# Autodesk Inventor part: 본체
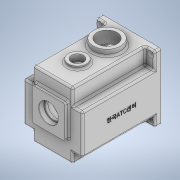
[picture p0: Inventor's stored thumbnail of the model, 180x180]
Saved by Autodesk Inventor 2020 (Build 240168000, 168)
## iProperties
Created: 2022-01
Part Number: 본체
Material: 일반
Document SubType Name: Modeling
Designer: user
Density: 1 g/cm^3
Appearance: 기본값
Author: user
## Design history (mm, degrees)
sketch "스케치5"
  geometry: L1 (-49, -55)-(49, -55); L2 (49, -55)-(49, 55); L3 (49, 55)-(-49, 55); L4 (-49, 55)-(-49, -55); L5 (-49, -55)-(49, 55); L6 (49, -55)-(-49, 55); 1 further point
  constraints: 12 end point, 2 midpoint, 2 parallel, 1 horizontal, 1 perpendicular
  dimensions: "d27" = 98 distance of L3.end L2.end; "d28" = 110 distance of L2.end L1.end
extrude "돌출6" new body sketch "스케치5" stored distance "d29" = 130; taper "d30" = 0 deg
sketch "스케치7"
  geometry: L1 (-49, 55)-(-49, -55) reference; L2 (-49, 55)-(-33, 55); L3 (-33, 55)-(-33, 28); L4 (-33, 28)-(-49, 28); L5 (-49, 28)-(-49, 55); L6 (49, 55)-(-49, 55) reference; L7 (49, 55)-(33, 55); L8 (33, 55)-(33, 28); L9 (33, 28)-(49, 28); L10 (49, 28)-(49, 55); L11 (49, -55)-(49, 55) reference; L12 (49, -55)-(33, -55); L13 (33, -55)-(33, -38); L14 (33, -38)-(49, -38); L15 (49, -38)-(49, -55); L16 (-49, -55)-(49, -55) reference; L17 (-49, -55)-(-33, -55); L18 (-33, -55)-(-33, -38); L19 (-33, -38)-(-49, -38); L20 (-49, -38)-(-49, -55); 6 further points
  constraints: 32 end point, 8 parallel, 4 horizontal, 4 perpendicular, 1 point on line
  dimensions: "d36" = 16 distance of L3.end L4.end; "d37" = 27 distance of L2.end L3.end; "d38" = 16 distance of L9.end L8.end; "d39" = 27 distance of L8.end L7.end; "d40" = 16 distance of L13.end L14.end; "d41" = 17 distance of L12.end L13.end; "d42" = 17 distance of L18.end L17.end
extrude "돌출8" cut sketch "스케치7" distance "d43" = 120; taper "d44" = 0 deg
sketch "스케치8"
  geometry: L1 (98, 0)-(0, 0) reference; L2 (49, 0)-(49, -40); L3 (49, -40)-(49, -89); C1 r 22.5 at (49, -40); C2 r 15 at (49, -89); 1 further point
  constraints: 4 end point, 2 centre point, 2 coincident, 1 midpoint, 1 point on line, 1 vertical
  dimensions: "d45" = 40 distance of L2.start L2.end; "d46" = 49 distance of L2.end L3.end; "d47" = 45 diameter of C1; "d48" = 30 diameter of C2
extrude "돌출9" join sketch "스케치8" distance "d49" = 5; taper "d50" = 0 deg
extrude "돌출10" join sketch "스케치8" distance "d51" = 10; taper "d52" = 0 deg
sketch "스케치9"
  geometry: L1 (0, 0)-(0, 11); L2 (33, -55)-(-33, -55) reference; L3 (0, -55)-(0, -5); L4 (0, 45)-(-23, 45); L5 (-23, 45)-(23, 45); L6 (23, 45)-(23, 33.249); L7 (-23, 33.249)-(-23, 45); A1 r 42 centre (0, -5) between (-25.375, 28.468) and (25.375, 28.468); A2 r 6 centre (-29, 33.249) between (-25.375, 28.468) and (-23, 33.249); A3 r 6 centre (29, 33.249) between (23, 33.249) and (25.375, 28.468); 4 further points
  constraints: 12 end point, 8 point on circle, 4 tangent, 3 centre point, 2 coincident, 2 horizontal, 2 point on line, 1 equal radius, 1 midpoint, 1 parallel, 1 perpendicular
  dimensions: "d63" = 50 distance of L3.start L3.end; "d64" = 84 diameter of A1; "d69" = 6 radius of A2 (derived)
extrude "돌출11" cut sketch "스케치9" distance "d70" = 121; taper "d71" = 0 deg
sketch "스케치10"
  geometry: L1 (-23, 33.249)-(-23, 45) reference; L2 (23, 45)-(23, 33.249) reference; L3 (-23, 45)-(23, 45) reference; L4 (26, 48)-(26, 33.249); L5 (-26, 33.249)-(-26, 48); L6 (-26, 48)-(26, 48); A1 r 42 centre (0, -5) between (-25.375, 28.468) and (25.375, 28.468) reference; A2 r 6 centre (-29, 33.249) between (-25.375, 28.468) and (-23, 33.249) reference; A3 r 42 centre (0, -5) between (-25.375, 28.468) and (25.375, 28.468) reference; A4 r 6 centre (29, 33.249) between (23, 33.249) and (25.375, 28.468) reference; A5 r 3 centre (29, 33.249) between (26, 33.249) and (27.188, 30.859); A6 r 45 centre (0, -5) between (-27.188, 30.859) and (27.188, 30.859); A7 r 3 centre (-29, 33.249) between (-27.188, 30.859) and (-26, 33.249); 3 further points
  constraints: 6 end point, 6 point on circle, 3 centre point, 5 other
  dimensions: "d72" = 3 distance between parallel lines of L3 L6
extrude "돌출12" cut sketch "스케치10" distance "d73" = 9; taper "d74" = 0 deg
sketch "스케치15"
  geometry: L1 (-33, -55)-(33, -55) reference; L2 (0, -55)-(0, 6); L3 (-27, -21)-(27, -21); L4 (27, -21)-(27, 33); L5 (27, 33)-(-27, 33); L6 (-27, 33)-(-27, -21); L7 (-27, -21)-(27, 33); L8 (27, -21)-(-27, 33); 1 further point
  constraints: 14 end point, 3 midpoint, 2 parallel, 1 horizontal, 1 perpendicular, 1 vertical
  dimensions: "d89" = 61 distance of L2.start L2.end; "d90" = 54 distance of L5.end L4.end; "d91" = 54 distance of L4.end L3.end
extrude "돌출14" join sketch "스케치15" distance "d92" = 7; taper "d93" = 0 deg
sketch "스케치16"
  geometry: L1 (27, -21)-(-27, -21) reference; L2 (0, -21)-(0, 6); C1 r 16 at (0, 6); 1 further point
  constraints: 2 end point, 1 centre point, 1 coincident, 1 midpoint, 1 vertical
  dimensions: "d94" = 27 distance of L2.start L2.end; "d95" = 32 diameter of C1
extrude "돌출15" cut sketch "스케치16" distance "d96" = 8.3; taper "d97" = 0 deg
chamfer "모따기2" distance "d98" = 0.8; stored, may be unused: second distance "d99" = 2, angle "d100" = 30 deg
sketch "스케치17"
  geometry: 1 further point
sketch "스케치18"
  geometry: L1 (33, -55)-(-33, -55) reference; L2 (0, -55)-(0, 6); L3 (23, 45)-(-23, 45) reference; C1 r 21 at (0, 6); C2 r 15 at (0, -25); 3 further points
  constraints: 2 centre point, 2 end point, 1 coincident, 1 midpoint, 1 vertical
  dimensions: "d101" = 61 distance of L2.start L2.end; "d102" = 42 diameter of C1; "d104" = 30 diameter of C2
extrude "돌출16" join sketch "스케치18" distance "d105" = 7; taper "d106" = 0 deg
sketch "스케치19"
  geometry: C1 r 16 at (0, 6) reference; C2 r 17.5 at (0, 6); A1 r 21 centre (0, 6) between (8.978, -12.984) and (-8.978, -12.984) reference; 1 further point
  constraints: 1 centre point, 1 coincident
  dimensions: "d107" = 35 diameter of C2
extrude "돌출17" cut sketch "스케치19" distance "d108" = 10; taper "d109" = 0 deg
sketch "스케치20"
  geometry: C1 r 14 at (0, 0); 1 further point
  constraints: 1 centre point
  dimensions: "d110" = 28 diameter of C1
extrude "돌출18" cut sketch "스케치20" distance "d111" = 10; taper "d112" = 0 deg
sketch "스케치21"
  geometry: 1 further point
sketch "스케치22"
  geometry: C1 r 11 at (0, -25); A1 r 15 centre (0, -25) between (-8.978, -12.984) and (8.978, -12.984) reference; 1 further point
  constraints: 1 centre point, 1 coincident
  dimensions: "d113" = 22 diameter of C1
extrude "돌출19" cut sketch "스케치22" distance "d114" = 7; taper "d115" = 0 deg
sketch "스케치23"
  geometry: C1 r 9.5 at (0, 0); 1 further point
  constraints: 1 centre point
  dimensions: "d116" = 19 diameter of C1
extrude "돌출20" cut sketch "스케치23" distance "d117" = 3; taper "d118" = 0 deg
sketch "스케치25"
  geometry: C1 r 15 at (23, -32) reference; C2 r 22.5 at (23, -81) reference; C3 r 15 at (23, -32); 1 further point
  constraints: 1 centre point, 1 coincident
  dimensions: "d120" = 30 diameter of C3
hole "구멍1" sketch "스케치25" at (23, -32) diameter "d121" = 20; stored, may be unused: countersink angle "d125" = 90 deg, drill point angle "d127" = 118 deg; dims "d122" = 4, "d123" = 30, "d124" = 5, "d126" = 20
sketch "스케치26"
  geometry: C1 r 22.5 at (0, 0) reference; 2 further points
  constraints: 1 coincident
hole "구멍2" sketch "스케치26" at (0, 0) diameter "d128" = 33.376; stored, may be unused: countersink angle "d132" = 90 deg, drill point angle "d134" = 118 deg; dims "d129" = 70, "d130" = 30, "d131" = 5, "d133" = 77.3
fillet "모깎기1" dims "d135" = 3
fillet "모깎기3" dims "d137" = 3
fillet "모깎기4" dims "d138" = 3
fillet "모깎기6" dims "d140" = 3
sketch "스케치27"
  geometry: 1 further point
sketch "스케치28"
  geometry: 1 further point
sketch "스케치29"
  geometry: 1 further point
sketch "스케치30"
  geometry: L1 (-49, 55)-(-49, -55) reference; L2 (-49, 55)-(-42, 55); L3 (-42, 55)-(-42, 48); L4 (-42, 48)-(-49, 48); L5 (-49, 48)-(-49, 55); L6 (-49, -55)-(49, -55) reference; L7 (-49, -55)-(-42, -55); L8 (-42, -55)-(-42, -48); L9 (-42, -48)-(-49, -48); L10 (-49, -48)-(-49, -55); L11 (49, -55)-(46, -55) reference; L12 (49, -55)-(42, -55); L13 (42, -55)-(42, -48); L14 (42, -48)-(49, -48); L15 (49, -48)-(49, -55); L16 (49, -55)-(49, 55) reference; L17 (49, 55)-(42, 55); L18 (42, 55)-(42, 48); L19 (42, 48)-(49, 48); L20 (49, 48)-(49, 55); 1 further point
  constraints: 32 end point, 8 parallel, 4 horizontal, 4 perpendicular
  dimensions: "d141" = 7 distance of L3.end L4.end; "d142" = 7 distance of L2.end L3.end; "d143" = 7 distance of L9.end L8.end; "d144" = 7 distance of L8.end L7.end; "d145" = 7 distance of L13.end L14.end; "d146" = 7 distance of L12.end L13.end; "d147" = 7 distance of L19.end L18.end; "d148" = 7 distance of L18.end L17.end
hole "구멍3" sketch "스케치30" at (-42, 48), (42, 48), (42, -48), (-42, -48) diameter "d149" = 10; stored, may be unused: countersink angle "d153" = 90 deg, drill point angle "d155" = 0 deg; dims "d150" = 70, "d151" = 30, "d152" = 5, "d154" = 10
fillet "모깎기7" dims "d156" = 3
sketch "스케치31"
  geometry: 1 further point
sketch "스케치32"
  geometry: L1 (-36, -1)-(-41.809, -1); L2 (-36, -9)-(-41.809, -9); A1 r 42 centre (0, -5) between (-25.375, 28.468) and (25.375, 28.468) reference; A2 r 4 centre (-36, -5) between (-36, -1) and (-36, -9); 1 further point
  constraints: 4 end point, 4 point on circle, 2 tangent, 1 centre point, 1 horizontal, 1 horizontal alignment, 1 parallel
  dimensions: "d157" = 36 distance of A2.centre A1.centre; "d158" = 8 diameter of A2
extrude "돌출21" join sketch "스케치32" stored distance "d159" = 3; taper "d160" = 0 deg
sketch "스케치33"
  geometry: 1 further point
sketch "스케치34"
  geometry: L1 (-130, 104)-(-130, 82) reference; L2 (-13, 107)-(-127, 107) reference; 2 further points
  constraints: 1 other
  dimensions: "d161" = 65 distance from line of L1 point (-65, 47); "d162" = 60 distance from line of L2 point (-65, 47)
feature "엠보싱1" sketch "스케치34" dims "d163" = 0.5, "d164" = 0
sketch "스케치35"
  geometry: A1 r 4 centre (-36, -5) between (-36, -9) and (-36, -1) reference; A2 r 4 centre (36, -5) between (36, -1) and (36, -9) reference; 3 further points
  constraints: 2 coincident
hole "구멍4" sketch "스케치35" at (-36, -5), (36, -5) diameter "d165" = 3.242; stored, may be unused: countersink angle "d169" = 90 deg, drill point angle "d171" = 118 deg; dims "d166" = 7, "d167" = 4, "d168" = 2, "d170" = 9
fillet "모깎기8" dims "d172" = 3
chamfer "모따기3" distance "d173" = 1; stored, may be unused: second distance "d174" = 2, angle "d175" = 45 deg
fillet "모깎기9" dims "d176" = 3
fillet "모깎기10" dims "d177" = 0.3
fillet "모깎기11" dims "d178" = 0.3
node "솔리드2"
mirror "미러1"
node "투영된 루프1"
node "투영된 루프2"
node "투영된 루프3"
feature "A9D066F2-1C7D-4E18-AEED-F7BC21143FA4" dims "d121" = 20, "d122" = 4, "d123" = 30, "d124" = 5, "d125" = 90 deg, "d126" = 20, "d127" = 118 deg
